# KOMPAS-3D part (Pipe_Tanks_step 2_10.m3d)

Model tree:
1. X Axis
2. Y Axis
3. Z Axis  (labels: Pipe Dn 50)
     Òîëùèíà ñòåíêè 1 = 1

Referenced files in C:\Documents and Settings\kashirsky\Мои документы\Camtasia Studio\Pipelines3D\Tanks\: Tanks_step 2.a3d
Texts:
  Pipe Dn 50
  Steel ASTM A295
  Three Point Plane
  Plane at Angle
  Line and Point Plane
  Axis through Two Vertices
  Axis of Feature
  Axis of Conical Surface
  Axis through Edge
  Trim by Surface
  Trim by Sketch
  Feature with No History
  Intersection Axis of Two Planes
  Two Line Plane
  Line and Face Plane
  Bend by line
  Hole in sheet body
  Cut in sheet body
  Point in CM
  Linear Dimension from Line to Point
  Surface Finish Symbol
  Geometric Tolerance Symbol
  Leader #1
  Leader #2
  Leader #3
  Shape Deviations and Datum
  Node point number
  Mark of coordination axis
  Node point designation
  Mark/Reference designation with leader
  Mark/reference designation on line
  Mark/Reference designation without leader
  Plane of section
